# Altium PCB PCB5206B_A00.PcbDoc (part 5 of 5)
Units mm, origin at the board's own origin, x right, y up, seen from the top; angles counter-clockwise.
Board outline 115 x 60 mm, 6 copper layers (Top Layer, GND Layer 2, Signal Layer 3, Signal Layer 4, VCC Layer 5, Bottom Layer), stack 1.555 mm thick; 384 components, 267 nets, 1313 pads, 834 vias.
Unrouted connection lines stored in the file: 10.
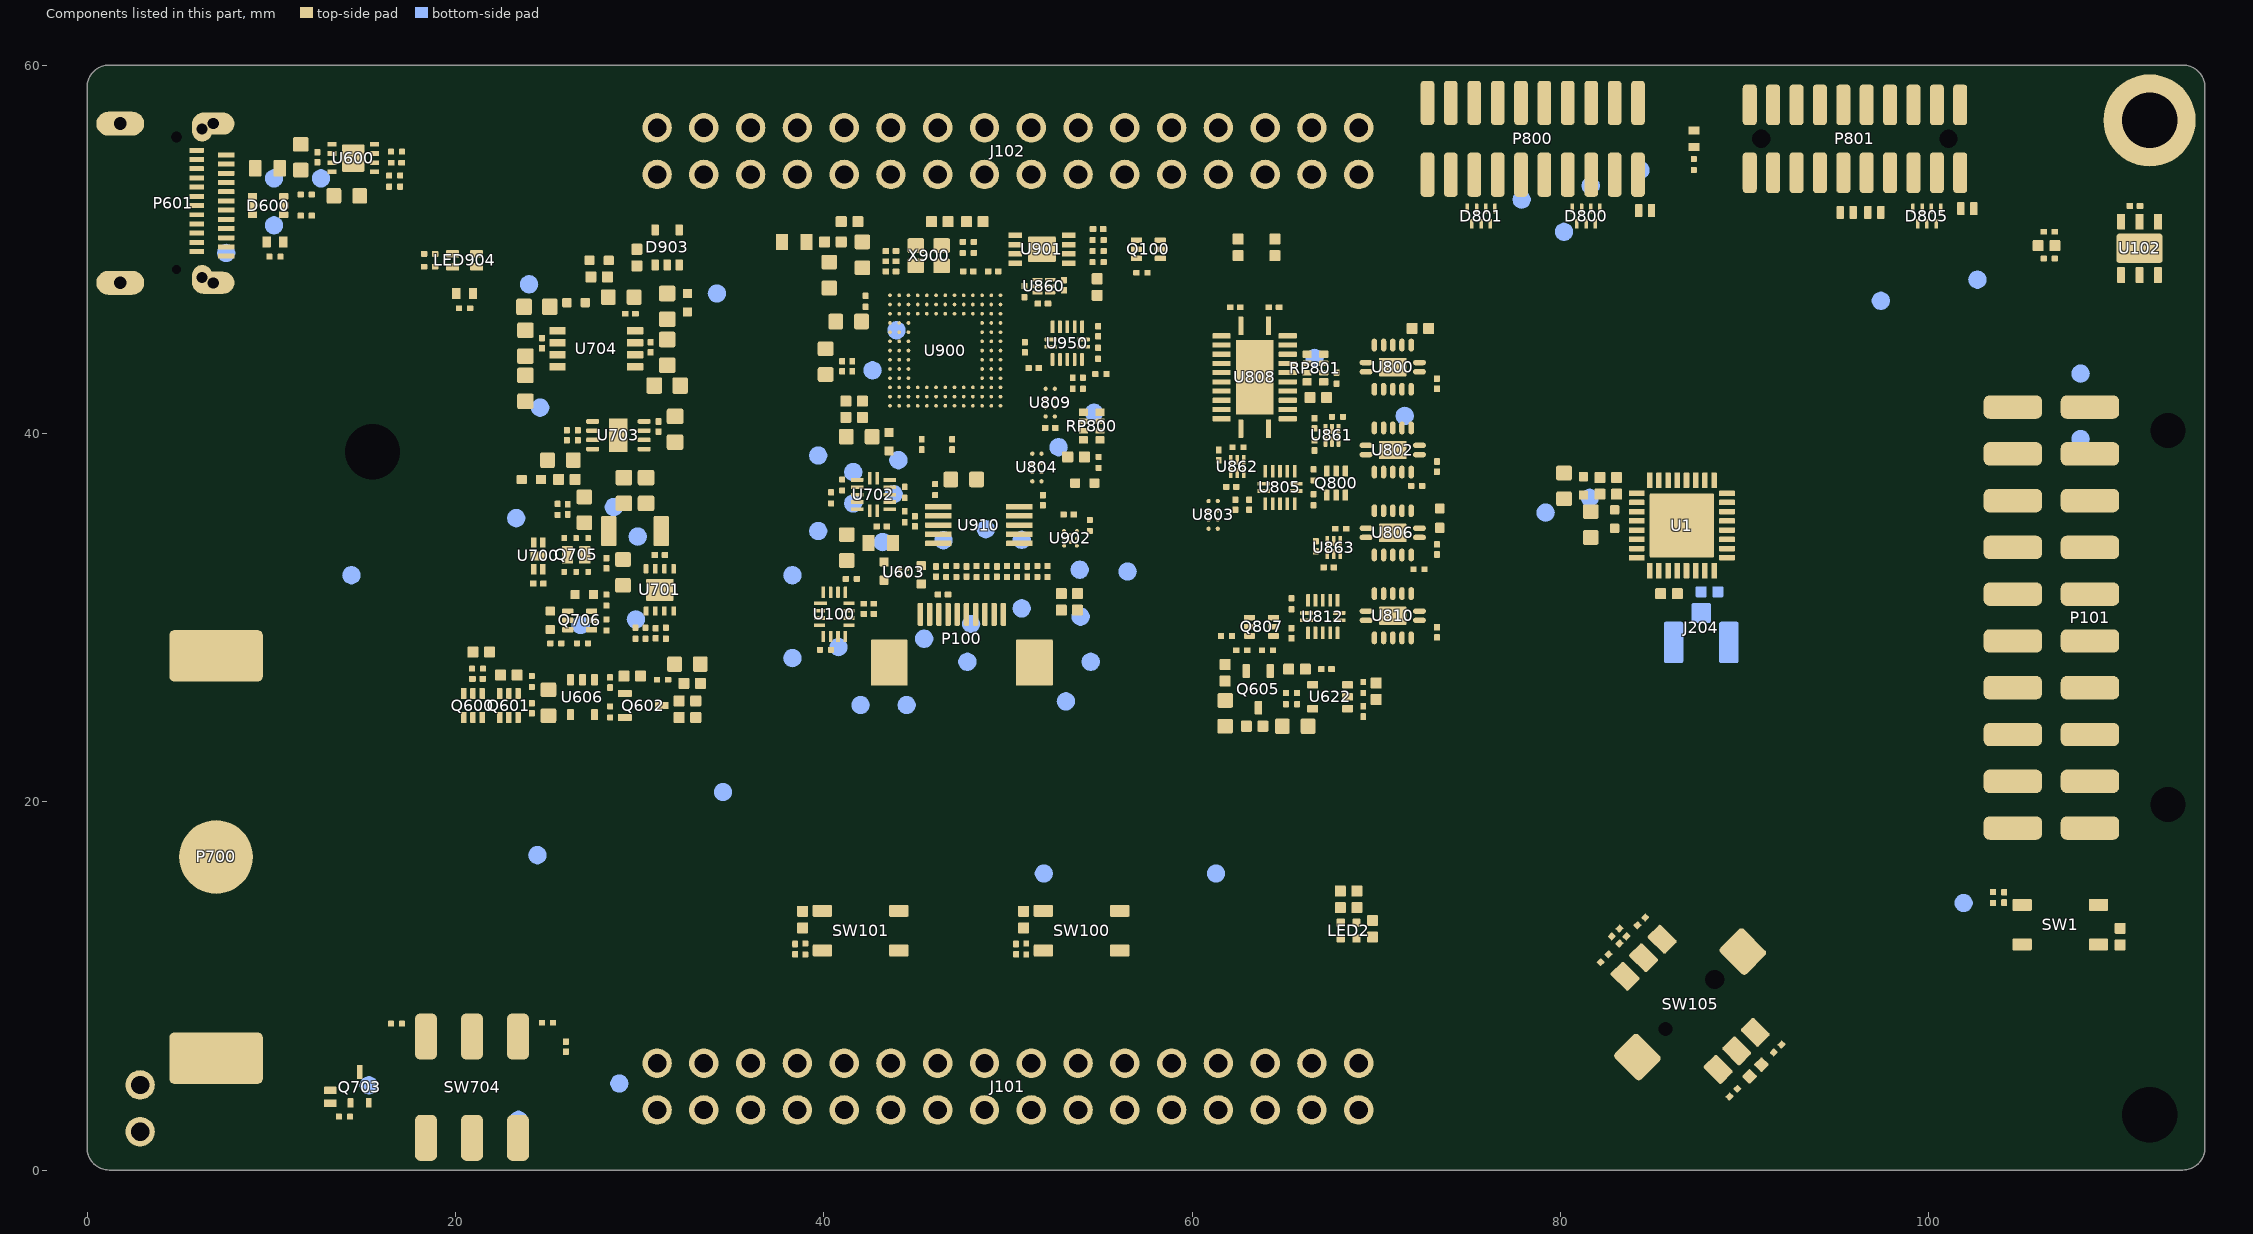
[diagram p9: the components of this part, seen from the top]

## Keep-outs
Bottom Layer:
  region: 32.691,5.802 ccw(c33.491,5.802) 33.491,5.002 ccw(c33.491,5.802) 34.291,5.802 ccw(c33.491,5.802) 33.491,6.602 ccw(c33.491,5.802)
  region: 35.231,5.802 ccw(c36.031,5.802) 36.031,5.002 ccw(c36.031,5.802) 36.831,5.802 ccw(c36.031,5.802) 36.031,6.602 ccw(c36.031,5.802)
  region: 37.771,5.802 ccw(c38.571,5.802) 38.571,5.002 ccw(c38.571,5.802) 39.371,5.802 ccw(c38.571,5.802) 38.571,6.602 ccw(c38.571,5.802)
  region: 40.311,5.802 ccw(c41.111,5.802) 41.111,5.002 ccw(c41.111,5.802) 41.911,5.802 ccw(c41.111,5.802) 41.111,6.602 ccw(c41.111,5.802)
  region: 42.851,5.802 ccw(c43.651,5.802) 43.651,5.002 ccw(c43.651,5.802) 44.451,5.802 ccw(c43.651,5.802) 43.651,6.602 ccw(c43.651,5.802)
  region: 45.391,5.802 ccw(c46.191,5.802) 46.191,5.002 ccw(c46.191,5.802) 46.991,5.802 ccw(c46.191,5.802) 46.191,6.602 ccw(c46.191,5.802)
  region: 47.931,5.802 ccw(c48.731,5.802) 48.731,5.002 ccw(c48.731,5.802) 49.531,5.802 ccw(c48.731,5.802) 48.731,6.602 ccw(c48.731,5.802)
  region: 50.471,5.802 ccw(c51.271,5.802) 51.271,5.002 ccw(c51.271,5.802) 52.071,5.802 ccw(c51.271,5.802) 51.271,6.602 ccw(c51.271,5.802)
  region: 53.011,5.802 ccw(c53.811,5.802) 53.811,5.002 ccw(c53.811,5.802) 54.611,5.802 ccw(c53.811,5.802) 53.811,6.602 ccw(c53.811,5.802)
  region: 55.551,5.802 ccw(c56.351,5.802) 56.351,5.002 ccw(c56.351,5.802) 57.151,5.802 ccw(c56.351,5.802) 56.351,6.602 ccw(c56.351,5.802)
  region: 58.091,5.802 ccw(c58.891,5.802) 58.891,5.002 ccw(c58.891,5.802) 59.691,5.802 ccw(c58.891,5.802) 58.891,6.602 ccw(c58.891,5.802)
  region: 60.631,5.802 ccw(c61.431,5.802) 61.431,5.002 ccw(c61.431,5.802) 62.231,5.802 ccw(c61.431,5.802) 61.431,6.602 ccw(c61.431,5.802)
  region: 63.171,5.802 ccw(c63.971,5.802) 63.971,5.002 ccw(c63.971,5.802) 64.771,5.802 ccw(c63.971,5.802) 63.971,6.602 ccw(c63.971,5.802)
  region: 65.711,5.802 ccw(c66.511,5.802) 66.511,5.002 ccw(c66.511,5.802) 67.311,5.802 ccw(c66.511,5.802) 66.511,6.602 ccw(c66.511,5.802)
  region: 68.251,5.802 ccw(c69.051,5.802) 69.051,5.002 ccw(c69.051,5.802) 69.851,5.802 ccw(c69.051,5.802) 69.051,6.602 ccw(c69.051,5.802)
  region: 30.151,5.802 ccw(c30.951,5.802) 30.951,5.002 ccw(c30.951,5.802) 31.751,5.802 ccw(c30.951,5.802) 30.951,6.602 ccw(c30.951,5.802)
  region: 30.151,3.262 ccw(c30.951,3.262) 30.951,2.462 ccw(c30.951,3.262) 31.751,3.262 ccw(c30.951,3.262) 30.951,4.062 ccw(c30.951,3.262)
  region: 30.151,3.262 ccw(c30.951,3.262) 30.951,2.462 ccw(c30.951,3.262) 31.751,3.262 ccw(c30.951,3.262) 30.951,4.062 ccw(c30.951,3.262)
  region: 32.691,3.262 ccw(c33.491,3.262) 33.491,2.462 ccw(c33.491,3.262) 34.291,3.262 ccw(c33.491,3.262) 33.491,4.062 ccw(c33.491,3.262)
  region: 35.231,3.262 ccw(c36.031,3.262) 36.031,2.462 ccw(c36.031,3.262) 36.831,3.262 ccw(c36.031,3.262) 36.031,4.062 ccw(c36.031,3.262)
  region: 37.771,3.262 ccw(c38.571,3.262) 38.571,2.462 ccw(c38.571,3.262) 39.371,3.262 ccw(c38.571,3.262) 38.571,4.062 ccw(c38.571,3.262)
  region: 40.311,3.262 ccw(c41.111,3.262) 41.111,2.462 ccw(c41.111,3.262) 41.911,3.262 ccw(c41.111,3.262) 41.111,4.062 ccw(c41.111,3.262)
  region: 42.851,3.262 ccw(c43.651,3.262) 43.651,2.462 ccw(c43.651,3.262) 44.451,3.262 ccw(c43.651,3.262) 43.651,4.062 ccw(c43.651,3.262)
  region: 45.391,3.262 ccw(c46.191,3.262) 46.191,2.462 ccw(c46.191,3.262) 46.991,3.262 ccw(c46.191,3.262) 46.191,4.062 ccw(c46.191,3.262)
  region: 47.931,3.262 ccw(c48.731,3.262) 48.731,2.462 ccw(c48.731,3.262) 49.531,3.262 ccw(c48.731,3.262) 48.731,4.062 ccw(c48.731,3.262)
  region: 50.471,3.262 ccw(c51.271,3.262) 51.271,2.462 ccw(c51.271,3.262) 52.071,3.262 ccw(c51.271,3.262) 51.271,4.062 ccw(c51.271,3.262)
  region: 53.011,3.262 ccw(c53.811,3.262) 53.811,2.462 ccw(c53.811,3.262) 54.611,3.262 ccw(c53.811,3.262) 53.811,4.062 ccw(c53.811,3.262)
  region: 55.551,3.262 ccw(c56.351,3.262) 56.351,2.462 ccw(c56.351,3.262) 57.151,3.262 ccw(c56.351,3.262) 56.351,4.062 ccw(c56.351,3.262)
  region: 58.091,3.262 ccw(c58.891,3.262) 58.891,2.462 ccw(c58.891,3.262) 59.691,3.262 ccw(c58.891,3.262) 58.891,4.062 ccw(c58.891,3.262)
  region: 60.631,3.262 ccw(c61.431,3.262) 61.431,2.462 ccw(c61.431,3.262) 62.231,3.262 ccw(c61.431,3.262) 61.431,4.062 ccw(c61.431,3.262)
  region: 63.171,3.262 ccw(c63.971,3.262) 63.971,2.462 ccw(c63.971,3.262) 64.771,3.262 ccw(c63.971,3.262) 63.971,4.062 ccw(c63.971,3.262)
  region: 65.711,3.262 ccw(c66.511,3.262) 66.511,2.462 ccw(c66.511,3.262) 67.311,3.262 ccw(c66.511,3.262) 66.511,4.062 ccw(c66.511,3.262)
  region: 68.251,3.262 ccw(c69.051,3.262) 69.051,2.462 ccw(c69.051,3.262) 69.851,3.262 ccw(c69.051,3.262) 69.051,4.062 ccw(c69.051,3.262)
  region: 32.691,56.602 ccw(c33.491,56.602) 33.491,55.802 ccw(c33.491,56.602) 34.291,56.602 ccw(c33.491,56.602) 33.491,57.402 ccw(c33.491,56.602)
  region: 35.231,56.602 ccw(c36.031,56.602) 36.031,55.802 ccw(c36.031,56.602) 36.831,56.602 ccw(c36.031,56.602) 36.031,57.402 ccw(c36.031,56.602)
  region: 37.771,56.602 ccw(c38.571,56.602) 38.571,55.802 ccw(c38.571,56.602) 39.371,56.602 ccw(c38.571,56.602) 38.571,57.402 ccw(c38.571,56.602)
  region: 40.311,56.602 ccw(c41.111,56.602) 41.111,55.802 ccw(c41.111,56.602) 41.911,56.602 ccw(c41.111,56.602) 41.111,57.402 ccw(c41.111,56.602)
  region: 42.851,56.602 ccw(c43.651,56.602) 43.651,55.802 ccw(c43.651,56.602) 44.451,56.602 ccw(c43.651,56.602) 43.651,57.402 ccw(c43.651,56.602)
  region: 45.391,56.602 ccw(c46.191,56.602) 46.191,55.802 ccw(c46.191,56.602) 46.991,56.602 ccw(c46.191,56.602) 46.191,57.402 ccw(c46.191,56.602)
  region: 47.931,56.602 ccw(c48.731,56.602) 48.731,55.802 ccw(c48.731,56.602) 49.531,56.602 ccw(c48.731,56.602) 48.731,57.402 ccw(c48.731,56.602)
  region: 50.471,56.602 ccw(c51.271,56.602) 51.271,55.802 ccw(c51.271,56.602) 52.071,56.602 ccw(c51.271,56.602) 51.271,57.402 ccw(c51.271,56.602)
  region: 53.011,56.602 ccw(c53.811,56.602) 53.811,55.802 ccw(c53.811,56.602) 54.611,56.602 ccw(c53.811,56.602) 53.811,57.402 ccw(c53.811,56.602)
  region: 55.551,56.602 ccw(c56.351,56.602) 56.351,55.802 ccw(c56.351,56.602) 57.151,56.602 ccw(c56.351,56.602) 56.351,57.402 ccw(c56.351,56.602)
  region: 58.091,56.602 ccw(c58.891,56.602) 58.891,55.802 ccw(c58.891,56.602) 59.691,56.602 ccw(c58.891,56.602) 58.891,57.402 ccw(c58.891,56.602)
  region: 60.631,56.602 ccw(c61.431,56.602) 61.431,55.802 ccw(c61.431,56.602) 62.231,56.602 ccw(c61.431,56.602) 61.431,57.402 ccw(c61.431,56.602)
  region: 63.171,56.602 ccw(c63.971,56.602) 63.971,55.802 ccw(c63.971,56.602) 64.771,56.602 ccw(c63.971,56.602) 63.971,57.402 ccw(c63.971,56.602)
  region: 65.711,56.602 ccw(c66.511,56.602) 66.511,55.802 ccw(c66.511,56.602) 67.311,56.602 ccw(c66.511,56.602) 66.511,57.402 ccw(c66.511,56.602)
  region: 68.251,56.602 ccw(c69.051,56.602) 69.051,55.802 ccw(c69.051,56.602) 69.851,56.602 ccw(c69.051,56.602) 69.051,57.402 ccw(c69.051,56.602)
  region: 30.151,56.602 ccw(c30.951,56.602) 30.951,55.802 ccw(c30.951,56.602) 31.751,56.602 ccw(c30.951,56.602) 30.951,57.402 ccw(c30.951,56.602)
  region: 30.151,54.062 ccw(c30.951,54.062) 30.951,53.262 ccw(c30.951,54.062) 31.751,54.062 ccw(c30.951,54.062) 30.951,54.862 ccw(c30.951,54.062)
  region: 30.151,54.062 ccw(c30.951,54.062) 30.951,53.262 ccw(c30.951,54.062) 31.751,54.062 ccw(c30.951,54.062) 30.951,54.862 ccw(c30.951,54.062)
  region: 32.691,54.062 ccw(c33.491,54.062) 33.491,53.262 ccw(c33.491,54.062) 34.291,54.062 ccw(c33.491,54.062) 33.491,54.862 ccw(c33.491,54.062)
  region: 35.231,54.062 ccw(c36.031,54.062) 36.031,53.262 ccw(c36.031,54.062) 36.831,54.062 ccw(c36.031,54.062) 36.031,54.862 ccw(c36.031,54.062)
  region: 37.771,54.062 ccw(c38.571,54.062) 38.571,53.262 ccw(c38.571,54.062) 39.371,54.062 ccw(c38.571,54.062) 38.571,54.862 ccw(c38.571,54.062)
  region: 40.311,54.062 ccw(c41.111,54.062) 41.111,53.262 ccw(c41.111,54.062) 41.911,54.062 ccw(c41.111,54.062) 41.111,54.862 ccw(c41.111,54.062)
  region: 42.851,54.062 ccw(c43.651,54.062) 43.651,53.262 ccw(c43.651,54.062) 44.451,54.062 ccw(c43.651,54.062) 43.651,54.862 ccw(c43.651,54.062)
  region: 45.391,54.062 ccw(c46.191,54.062) 46.191,53.262 ccw(c46.191,54.062) 46.991,54.062 ccw(c46.191,54.062) 46.191,54.862 ccw(c46.191,54.062)
  region: 47.931,54.062 ccw(c48.731,54.062) 48.731,53.262 ccw(c48.731,54.062) 49.531,54.062 ccw(c48.731,54.062) 48.731,54.862 ccw(c48.731,54.062)
  region: 50.471,54.062 ccw(c51.271,54.062) 51.271,53.262 ccw(c51.271,54.062) 52.071,54.062 ccw(c51.271,54.062) 51.271,54.862 ccw(c51.271,54.062)
  region: 53.011,54.062 ccw(c53.811,54.062) 53.811,53.262 ccw(c53.811,54.062) 54.611,54.062 ccw(c53.811,54.062) 53.811,54.862 ccw(c53.811,54.062)
  region: 55.551,54.062 ccw(c56.351,54.062) 56.351,53.262 ccw(c56.351,54.062) 57.151,54.062 ccw(c56.351,54.062) 56.351,54.862 ccw(c56.351,54.062)
  region: 58.091,54.062 ccw(c58.891,54.062) 58.891,53.262 ccw(c58.891,54.062) 59.691,54.062 ccw(c58.891,54.062) 58.891,54.862 ccw(c58.891,54.062)
  region: 60.631,54.062 ccw(c61.431,54.062) 61.431,53.262 ccw(c61.431,54.062) 62.231,54.062 ccw(c61.431,54.062) 61.431,54.862 ccw(c61.431,54.062)
  region: 63.171,54.062 ccw(c63.971,54.062) 63.971,53.262 ccw(c63.971,54.062) 64.771,54.062 ccw(c63.971,54.062) 63.971,54.862 ccw(c63.971,54.062)
  region: 65.711,54.062 ccw(c66.511,54.062) 66.511,53.262 ccw(c66.511,54.062) 67.311,54.062 ccw(c66.511,54.062) 66.511,54.862 ccw(c66.511,54.062)
  region: 68.251,54.062 ccw(c69.051,54.062) 69.051,53.262 ccw(c69.051,54.062) 69.851,54.062 ccw(c69.051,54.062) 69.051,54.862 ccw(c69.051,54.062)
  region: 45.391,54.062 ccw(c46.191,54.062) 46.191,53.262 ccw(c46.191,54.062) 46.991,54.062 ccw(c46.191,54.062) 46.191,54.862 ccw(c46.191,54.062)
  region: 42.851,54.062 ccw(c43.651,54.062) 43.651,53.262 ccw(c43.651,54.062) 44.451,54.062 ccw(c43.651,54.062) 43.651,54.862 ccw(c43.651,54.062)
  region: 40.311,54.062 ccw(c41.111,54.062) 41.111,53.262 ccw(c41.111,54.062) 41.911,54.062 ccw(c41.111,54.062) 41.111,54.862 ccw(c41.111,54.062)
  region: 37.771,54.062 ccw(c38.571,54.062) 38.571,53.262 ccw(c38.571,54.062) 39.371,54.062 ccw(c38.571,54.062) 38.571,54.862 ccw(c38.571,54.062)
  region: 35.231,54.062 ccw(c36.031,54.062) 36.031,53.262 ccw(c36.031,54.062) 36.831,54.062 ccw(c36.031,54.062) 36.031,54.862 ccw(c36.031,54.062)
  region: 32.691,54.062 ccw(c33.491,54.062) 33.491,53.262 ccw(c33.491,54.062) 34.291,54.062 ccw(c33.491,54.062) 33.491,54.862 ccw(c33.491,54.062)
  region: 30.151,54.062 ccw(c30.951,54.062) 30.951,53.262 ccw(c30.951,54.062) 31.751,54.062 ccw(c30.951,54.062) 30.951,54.862 ccw(c30.951,54.062)
  region: 30.151,54.062 ccw(c30.951,54.062) 30.951,53.262 ccw(c30.951,54.062) 31.751,54.062 ccw(c30.951,54.062) 30.951,54.862 ccw(c30.951,54.062)
  region: 30.151,56.602 ccw(c30.951,56.602) 30.951,55.802 ccw(c30.951,56.602) 31.751,56.602 ccw(c30.951,56.602) 30.951,57.402 ccw(c30.951,56.602)
  region: 45.391,56.602 ccw(c46.191,56.602) 46.191,55.802 ccw(c46.191,56.602) 46.991,56.602 ccw(c46.191,56.602) 46.191,57.402 ccw(c46.191,56.602)
  region: 42.851,56.602 ccw(c43.651,56.602) 43.651,55.802 ccw(c43.651,56.602) 44.451,56.602 ccw(c43.651,56.602) 43.651,57.402 ccw(c43.651,56.602)
  region: 40.311,56.602 ccw(c41.111,56.602) 41.111,55.802 ccw(c41.111,56.602) 41.911,56.602 ccw(c41.111,56.602) 41.111,57.402 ccw(c41.111,56.602)
  region: 37.771,56.602 ccw(c38.571,56.602) 38.571,55.802 ccw(c38.571,56.602) 39.371,56.602 ccw(c38.571,56.602) 38.571,57.402 ccw(c38.571,56.602)
  region: 35.231,56.602 ccw(c36.031,56.602) 36.031,55.802 ccw(c36.031,56.602) 36.831,56.602 ccw(c36.031,56.602) 36.031,57.402 ccw(c36.031,56.602)
  region: 32.691,56.602 ccw(c33.491,56.602) 33.491,55.802 ccw(c33.491,56.602) 34.291,56.602 ccw(c33.491,56.602) 33.491,57.402 ccw(c33.491,56.602)
  region: 68.251,3.262 ccw(c69.051,3.262) 69.051,2.462 ccw(c69.051,3.262) 69.851,3.262 ccw(c69.051,3.262) 69.051,4.062 ccw(c69.051,3.262)
  region: 65.711,3.262 ccw(c66.511,3.262) 66.511,2.462 ccw(c66.511,3.262) 67.311,3.262 ccw(c66.511,3.262) 66.511,4.062 ccw(c66.511,3.262)
  region: 60.631,3.262 ccw(c61.431,3.262) 61.431,2.462 ccw(c61.431,3.262) 62.231,3.262 ccw(c61.431,3.262) 61.431,4.062 ccw(c61.431,3.262)
  region: 58.091,3.262 ccw(c58.891,3.262) 58.891,2.462 ccw(c58.891,3.262) 59.691,3.262 ccw(c58.891,3.262) 58.891,4.062 ccw(c58.891,3.262)
  region: 40.311,3.262 ccw(c41.111,3.262) 41.111,2.462 ccw(c41.111,3.262) 41.911,3.262 ccw(c41.111,3.262) 41.111,4.062 ccw(c41.111,3.262)
  region: 37.771,3.262 ccw(c38.571,3.262) 38.571,2.462 ccw(c38.571,3.262) 39.371,3.262 ccw(c38.571,3.262) 38.571,4.062 ccw(c38.571,3.262)
  region: 35.231,3.262 ccw(c36.031,3.262) 36.031,2.462 ccw(c36.031,3.262) 36.831,3.262 ccw(c36.031,3.262) 36.031,4.062 ccw(c36.031,3.262)
  region: 32.691,3.262 ccw(c33.491,3.262) 33.491,2.462 ccw(c33.491,3.262) 34.291,3.262 ccw(c33.491,3.262) 33.491,4.062 ccw(c33.491,3.262)
  region: 30.151,3.262 ccw(c30.951,3.262) 30.951,2.462 ccw(c30.951,3.262) 31.751,3.262 ccw(c30.951,3.262) 30.951,4.062 ccw(c30.951,3.262)
  region: 30.151,3.262 ccw(c30.951,3.262) 30.951,2.462 ccw(c30.951,3.262) 31.751,3.262 ccw(c30.951,3.262) 30.951,4.062 ccw(c30.951,3.262)
  region: 30.151,5.802 ccw(c30.951,5.802) 30.951,5.002 ccw(c30.951,5.802) 31.751,5.802 ccw(c30.951,5.802) 30.951,6.602 ccw(c30.951,5.802)
  region: 68.251,5.802 ccw(c69.051,5.802) 69.051,5.002 ccw(c69.051,5.802) 69.851,5.802 ccw(c69.051,5.802) 69.051,6.602 ccw(c69.051,5.802)
  region: 65.711,5.802 ccw(c66.511,5.802) 66.511,5.002 ccw(c66.511,5.802) 67.311,5.802 ccw(c66.511,5.802) 66.511,6.602 ccw(c66.511,5.802)
  region: 63.171,5.802 ccw(c63.971,5.802) 63.971,5.002 ccw(c63.971,5.802) 64.771,5.802 ccw(c63.971,5.802) 63.971,6.602 ccw(c63.971,5.802)
  region: 60.631,5.802 ccw(c61.431,5.802) 61.431,5.002 ccw(c61.431,5.802) 62.231,5.802 ccw(c61.431,5.802) 61.431,6.602 ccw(c61.431,5.802)
  region: 58.091,5.802 ccw(c58.891,5.802) 58.891,5.002 ccw(c58.891,5.802) 59.691,5.802 ccw(c58.891,5.802) 58.891,6.602 ccw(c58.891,5.802)
  region: 40.311,5.802 ccw(c41.111,5.802) 41.111,5.002 ccw(c41.111,5.802) 41.911,5.802 ccw(c41.111,5.802) 41.111,6.602 ccw(c41.111,5.802)
  region: 37.771,5.802 ccw(c38.571,5.802) 38.571,5.002 ccw(c38.571,5.802) 39.371,5.802 ccw(c38.571,5.802) 38.571,6.602 ccw(c38.571,5.802)
  region: 35.231,5.802 ccw(c36.031,5.802) 36.031,5.002 ccw(c36.031,5.802) 36.831,5.802 ccw(c36.031,5.802) 36.031,6.602 ccw(c36.031,5.802)
  region: 32.691,5.802 ccw(c33.491,5.802) 33.491,5.002 ccw(c33.491,5.802) 34.291,5.802 ccw(c33.491,5.802) 33.491,6.602 ccw(c33.491,5.802)
  region: 103.5,19 cw(c103.5,18.5) 104,18.5 cw(c103.5,18.5) 103.5,18 cw(c103.5,18.5) 103,18.5 cw(c103.5,18.5)
  region: 108.25,40.2 cw(c108.25,39.699) 108.75,39.7 cw(c108.25,39.7) 108.25,39.2 cw(c108.25,39.7) 107.75,39.7 cw(c108.25,39.699)
  region: 108.25,43.748 cw(c108.25,43.248) 108.75,43.248 cw(c108.25,43.248) 108.25,42.748 cw(c108.25,43.248) 107.75,43.248 cw(c108.25,43.248)
  region: 107,54.2 cw(c107,53.7) 107.5,53.7 cw(c107,53.7) 107,53.2 cw(c107,53.7) 106.5,53.7 cw(c107,53.7)
  region: 105.4,52.498 cw(c105.4,51.998) 105.9,51.998 cw(c105.4,51.998) 105.4,51.498 cw(c105.4,51.998) 104.9,51.998 cw(c105.4,51.998)
  region: 104.45,54.2 cw(c104.45,53.7) 104.95,53.7 cw(c104.45,53.7) 104.45,53.2 cw(c104.45,53.7) 103.95,53.7 cw(c104.45,53.7)
  region: 103.399,52.498 cw(c103.399,51.998) 103.899,51.998 cw(c103.399,51.998) 103.399,51.498 cw(c103.399,51.998) 102.899,51.998 cw(c103.399,51.998)
  region: 102.649,48.848 cw(c102.649,48.348) 103.149,48.348 cw(c102.649,48.348) 102.649,47.848 cw(c102.649,48.348) 102.149,48.348 cw(c102.649,48.348)
  region: 97.399,47.7 cw(c97.399,47.2) 97.899,47.2 cw(c97.399,47.2) 97.399,46.7 cw(c97.399,47.2) 96.899,47.2 cw(c97.399,47.2)
  region: 92.525,52.432 cw(c92.525,51.932) 93.025,51.932 cw(c92.525,51.932) 92.525,51.432 cw(c92.525,51.932) 92.025,51.932 cw(c92.525,51.932)
  region: 93.541,54.21 cw(c93.541,53.71) 94.041,53.71 cw(c93.541,53.71) 93.541,53.21 cw(c93.541,53.71) 93.041,53.71 cw(c93.541,53.71)
  region: 90.493,52.432 cw(c90.493,51.932) 90.993,51.932 cw(c90.493,51.932) 90.493,51.432 cw(c90.493,51.932) 89.993,51.932 cw(c90.493,51.932)
  region: 88.461,52.432 cw(c88.461,51.932) 88.961,51.932 cw(c88.461,51.932) 88.461,51.432 cw(c88.461,51.932) 87.961,51.932 cw(c88.461,51.932)
  region: 89.477,54.21 cw(c89.477,53.71) 89.977,53.71 cw(c89.477,53.71) 89.477,53.21 cw(c89.477,53.71) 88.977,53.71 cw(c89.477,53.71)
  region: 87.466,54.206 cw(c87.467,53.706) 87.967,53.706 cw(c87.466,53.707) 87.466,53.206 cw(c87.466,53.706) 86.967,53.706 cw(c87.467,53.706)
  region: 84.349,54.799 cw(c84.349,54.299) 84.849,54.3 cw(c84.349,54.3) 84.349,53.799 cw(c84.349,54.299) 83.849,54.299 cw(c84.349,54.299)
  region: 85.4,52.198 cw(c85.4,51.698) 85.9,51.699 cw(c85.4,51.699) 85.4,51.199 cw(c85.4,51.698) 84.9,51.698 cw(c85.4,51.698)
  region: 93.449,42.798 cw(c93.45,42.298) 93.95,42.298 cw(c93.449,42.298) 93.449,41.798 cw(c93.449,42.298) 92.949,42.298 cw(c93.45,42.298)
  region: 86.15,40.05 cw(c86.15,39.55) 86.65,39.55 cw(c86.149,39.55) 86.149,39.05 cw(c86.149,39.55) 85.65,39.55 cw(c86.15,39.55)
  region: 81.649,53.949 cw(c81.649,53.449) 82.149,53.449 cw(c81.649,53.449) 81.649,52.949 cw(c81.649,53.449) 81.149,53.449 cw(c81.649,53.448)
  region: 77.9,53.199 cw(c77.9,52.699) 78.4,52.699 cw(c77.9,52.699) 77.9,52.199 cw(c77.9,52.699) 77.4,52.699 cw(c77.9,52.699)
  region: 80.201,51.449 cw(c80.201,50.949) 80.701,50.949 cw(c80.201,50.949) 80.201,50.449 cw(c80.201,50.949) 79.701,50.949 cw(c80.201,50.949)
  region: 77.399,48.498 cw(c77.399,47.998) 77.899,47.998 cw(c77.399,47.998) 77.399,47.498 cw(c77.399,47.998) 76.899,47.998 cw(c77.399,47.998)
  region: 75.4,48.498 cw(c75.4,47.998) 75.9,47.998 cw(c75.4,47.998) 75.4,47.498 cw(c75.4,47.998) 74.9,47.998 cw(c75.4,47.998)
  region: 73.399,48.498 cw(c73.399,47.998) 73.899,47.998 cw(c73.399,47.998) 73.399,47.498 cw(c73.399,47.998) 72.899,47.998 cw(c73.399,47.998)
  region: 77.399,46.298 cw(c77.399,45.798) 77.899,45.798 cw(c77.399,45.798) 77.399,45.298 cw(c77.399,45.798) 76.899,45.798 cw(c77.399,45.798)
  region: 75.4,46.298 cw(c75.4,45.798) 75.9,45.798 cw(c75.4,45.798) 75.4,45.298 cw(c75.4,45.798) 74.9,45.798 cw(c75.4,45.798)
  region: 73.399,46.298 cw(c73.399,45.798) 73.899,45.798 cw(c73.399,45.798) 73.399,45.298 cw(c73.399,45.798) 72.899,45.798 cw(c73.399,45.798)
  region: 71.4,46.298 cw(c71.4,45.798) 71.9,45.798 cw(c71.4,45.798) 71.4,45.298 cw(c71.4,45.798) 70.9,45.798 cw(c71.4,45.798)
  region: 73.399,43.598 cw(c73.399,43.098) 73.899,43.098 cw(c73.399,43.098) 73.399,42.598 cw(c73.399,43.098) 72.899,43.098 cw(c73.399,43.098)
  region: 71.55,41.449 cw(c71.55,40.949) 72.05,40.949 cw(c71.55,40.949) 71.55,40.449 cw(c71.55,40.949) 71.05,40.949 cw(c71.55,40.949)
  region: 66.65,44.599 cw(c66.65,44.099) 67.15,44.099 cw(c66.65,44.099) 66.65,43.599 cw(c66.65,44.099) 66.15,44.099 cw(c66.65,44.099)
  region: 94.199,12.348 cw(c94.199,11.848) 94.699,11.848 cw(c94.199,11.849) 94.199,11.348 cw(c94.199,11.848) 93.699,11.848 cw(c94.199,11.848)
  region: 96.8,11.8 cw(c96.8,11.3) 97.3,11.3 cw(c96.8,11.3) 96.8,10.8 cw(c96.8,11.3) 96.3,11.3 cw(c96.8,11.3)
  region: 93.249,9.948 cw(c93.249,9.448) 93.749,9.448 cw(c93.249,9.448) 93.249,8.948 cw(c93.249,9.448) 92.749,9.448 cw(c93.249,9.448)
  region: 96.5,9.148 cw(c96.5,8.648) 97,8.648 cw(c96.5,8.648) 96.5,8.148 cw(c96.5,8.648) 96,8.648 cw(c96.5,8.648)
  region: 95.7,6.55 cw(c95.7,6.05) 96.2,6.05 cw(c95.7,6.05) 95.7,5.55 cw(c95.7,6.05) 95.2,6.05 cw(c95.7,6.049)
  region: 93.249,7.398 cw(c93.249,6.898) 93.749,6.898 cw(c93.249,6.898) 93.249,6.398 cw(c93.249,6.898) 92.749,6.898 cw(c93.249,6.898)
  region: 81.499,10.949 cw(c81.499,10.449) 81.999,10.449 cw(c81.499,10.449) 81.499,9.949 cw(c81.499,10.449) 80.999,10.449 cw(c81.499,10.449)
  region: 77.249,10.949 cw(c77.249,10.449) 77.749,10.449 cw(c77.249,10.449) 77.249,9.949 cw(c77.249,10.449) 76.749,10.449 cw(c77.249,10.449)
  region: 72.949,10.949 cw(c72.949,10.449) 73.449,10.449 cw(c72.949,10.449) 72.949,9.949 cw(c72.949,10.449) 72.449,10.449 cw(c72.949,10.449)
  region: 74.1,6.748 cw(c74.1,6.248) 74.6,6.248 cw(c74.1,6.248) 74.1,5.748 cw(c74.1,6.248) 73.6,6.248 cw(c74.1,6.248)
  region: 54.674,41.624 cw(c54.674,41.124) 55.174,41.125 cw(c54.674,41.125) 54.674,40.625 cw(c54.674,41.124) 54.174,41.124 cw(c54.674,41.124)
  region: 52.749,39.75 cw(c52.749,39.25) 53.249,39.25 cw(c52.748,39.25) 52.748,38.75 cw(c52.748,39.25) 52.249,39.25 cw(c52.749,39.25)
  region: 50.75,34.723 cw(c50.75,34.223) 51.25,34.223 cw(c50.749,34.223) 50.75,33.723 cw(c50.75,34.223) 50.25,34.223 cw(c50.75,34.223)
  region: 53.899,33.098 cw(c53.899,32.598) 54.399,32.598 cw(c53.899,32.598) 53.899,32.098 cw(c53.899,32.598) 53.399,32.598 cw(c53.899,32.598)
  region: 50.75,31 cw(c50.75,30.5) 51.25,30.5 cw(c50.749,30.5) 50.75,30 cw(c50.75,30.5) 50.25,30.5 cw(c50.75,30.5)
  region: 53.95,30.55 cw(c53.95,30.05) 54.45,30.05 cw(c53.95,30.05) 53.95,29.55 cw(c53.95,30.05) 53.45,30.05 cw(c53.95,30.05)
  region: 54.499,28.099 cw(c54.499,27.599) 54.999,27.599 cw(c54.498,27.599) 54.499,27.099 cw(c54.499,27.599) 53.999,27.599 cw(c54.499,27.599)
  region: 51.799,28.099 cw(c51.799,27.599) 52.299,27.599 cw(c51.798,27.599) 51.799,27.099 cw(c51.799,27.599) 51.299,27.599 cw(c51.799,27.599)
  region: 53.15,25.95 cw(c53.15,25.45) 53.65,25.45 cw(c53.15,25.45) 53.15,24.95 cw(c53.15,25.45) 52.65,25.45 cw(c53.15,25.45)
  region: 47.999,30.149 cw(c47.999,29.649) 48.499,29.649 cw(c47.999,29.649) 47.999,29.149 cw(c47.999,29.649) 47.499,29.649 cw(c47.999,29.649)
  region: 45.449,29.349 cw(c45.449,28.849) 45.949,28.849 cw(c45.448,28.849) 45.449,28.349 cw(c45.449,28.849) 44.949,28.849 cw(c45.449,28.849)
  region: 47,25.749 cw(c47.001,25.249) 47.501,25.25 cw(c47,25.25) 47,24.75 cw(c47,25.249) 46.501,25.249 cw(c47.001,25.249)
  region: 43.249,28 cw(c43.249,27.5) 43.749,27.5 cw(c43.249,27.5) 43.249,27 cw(c43.249,27.5) 42.749,27.5 cw(c43.249,27.5)
  region: 44.499,25.749 cw(c44.499,25.249) 44.999,25.25 cw(c44.499,25.25) 44.499,24.75 cw(c44.499,25.249) 43.999,25.249 cw(c44.499,25.249)
  region: 41.999,25.749 cw(c41.999,25.249) 42.499,25.25 cw(c41.999,25.25) 41.999,24.75 cw(c41.999,25.249) 41.499,25.249 cw(c41.999,25.249)
  region: 61.301,16.598 cw(c61.301,16.098) 61.801,16.098 cw(c61.301,16.098) 61.301,15.598 cw(c61.301,16.098) 60.801,16.098 cw(c61.301,16.098)
  region: 51.951,16.598 cw(c51.951,16.098) 52.451,16.098 cw(c51.951,16.098) 51.951,15.598 cw(c51.951,16.098) 51.451,16.098 cw(c51.951,16.098)
  region: 34.524,21.025 cw(c34.524,20.525) 35.024,20.525 cw(c34.524,20.525) 34.524,20.025 cw(c34.524,20.525) 34.024,20.525 cw(c34.524,20.525)
  region: 24.45,17.599 cw(c24.45,17.099) 24.95,17.099 cw(c24.45,17.099) 24.45,16.599 cw(c24.45,17.099) 23.95,17.099 cw(c24.45,17.098)
  region: 15.649,26.448 cw(c15.649,25.948) 16.149,25.948 cw(c15.649,25.948) 15.649,25.448 cw(c15.649,25.948) 15.149,25.948 cw(c15.649,25.948)
  region: 12.05,26.448 cw(c12.05,25.948) 12.55,25.948 cw(c12.05,25.948) 12.05,25.448 cw(c12.05,25.948) 11.55,25.948 cw(c12.05,25.948)
  region: 12.025,29.773 cw(c12.025,29.273) 12.525,29.273 cw(c12.025,29.273) 12.025,28.773 cw(c12.025,29.273) 11.525,29.273 cw(c12.025,29.273)
  region: 9.475,29.798 cw(c9.475,29.298) 9.975,29.298 cw(c9.474,29.298) 9.475,28.798 cw(c9.475,29.298) 8.975,29.298 cw(c9.475,29.298)
  region: 14.349,32.798 cw(c14.349,32.298) 14.849,32.298 cw(c14.349,32.298) 14.349,31.798 cw(c14.349,32.298) 13.849,32.298 cw(c14.349,32.298)
  region: 10.399,32.249 cw(c10.399,31.749) 10.899,31.749 cw(c10.399,31.75) 10.399,31.249 cw(c10.399,31.749) 9.899,31.749 cw(c10.399,31.749)
  region: 10.399,34.899 cw(c10.399,34.399) 10.899,34.399 cw(c10.399,34.399) 10.399,33.899 cw(c10.399,34.399) 9.899,34.399 cw(c10.399,34.398)
  region: 18.446,49.044 cw(c18.446,48.544) 18.946,48.544 cw(c18.446,48.544) 18.446,48.044 cw(c18.446,48.544) 17.946,48.544 cw(c18.446,48.544)
  region: 15.906,50.314 cw(c15.906,49.814) 16.406,49.814 cw(c15.906,49.814) 15.906,49.314 cw(c15.906,49.814) 15.406,49.814 cw(c15.906,49.814)
  region: 18.446,51.584 cw(c18.446,51.084) 18.946,51.084 cw(c18.446,51.084) 18.446,50.584 cw(c18.446,51.084) 17.946,51.084 cw(c18.446,51.084)
  region: 15.906,52.854 cw(c15.906,52.354) 16.406,52.354 cw(c15.906,52.354) 15.906,51.854 cw(c15.906,52.354) 15.406,52.354 cw(c15.906,52.354)
  region: 18.446,54.124 cw(c18.446,53.624) 18.946,53.624 cw(c18.446,53.624) 18.446,53.124 cw(c18.446,53.624) 17.946,53.624 cw(c18.446,53.624)
  region: 15.906,55.394 cw(c15.906,54.894) 16.406,54.894 cw(c15.906,54.894) 15.906,54.394 cw(c15.906,54.894) 15.406,54.894 cw(c15.906,54.894)
  region: 12.7,54.35 cw(c12.7,53.85) 13.2,53.85 cw(c12.7,53.85) 12.7,53.35 cw(c12.7,53.85) 12.2,53.85 cw(c12.7,53.85)
  region: 10.15,54.35 cw(c10.15,53.85) 10.65,53.85 cw(c10.15,53.85) 10.15,53.35 cw(c10.15,53.85) 9.65,53.85 cw(c10.15,53.85)
  region: 10.15,51.8 cw(c10.15,51.3) 10.65,51.3 cw(c10.15,51.3) 10.15,50.8 cw(c10.15,51.3) 9.65,51.3 cw(c10.15,51.3)
  region: 7.549,50.299 cw(c7.549,49.799) 8.049,49.799 cw(c7.549,49.799) 7.549,49.299 cw(c7.549,49.799) 7.049,49.799 cw(c7.549,49.798)
  region: 24.6,41.899 cw(c24.6,41.399) 25.1,41.399 cw(c24.6,41.399) 24.6,40.899 cw(c24.6,41.399) 24.1,41.399 cw(c24.6,41.399)
  region: 36.249,37.548 cw(c36.249,37.048) 36.749,37.048 cw(c36.249,37.048) 36.249,36.548 cw(c36.249,37.048) 35.749,37.048 cw(c36.249,37.048)
  region: 38.999,37.548 cw(c39,37.048) 39.5,37.048 cw(c38.999,37.048) 38.999,36.548 cw(c38.999,37.048) 38.5,37.048 cw(c39,37.048)
  region: 41.6,38.399 cw(c41.6,37.899) 42.101,37.899 cw(c41.6,37.899) 41.6,37.399 cw(c41.6,37.899) 41.1,37.899 cw(c41.601,37.899)
  region: 44.049,39.049 cw(c44.049,38.549) 44.549,38.549 cw(c44.049,38.549) 44.049,38.049 cw(c44.049,38.549) 43.549,38.549 cw(c44.049,38.549)
  region: 42.649,43.923 cw(c42.65,43.423) 43.15,43.423 cw(c42.649,43.423) 42.649,42.923 cw(c42.649,43.423) 42.149,43.423 cw(c42.65,43.423)
  region: 43.95,46.1 cw(c43.95,45.6) 44.45,45.6 cw(c43.95,45.6) 43.95,45.1 cw(c43.95,45.6) 43.45,45.6 cw(c43.95,45.6)
  region: 18.446,46.504 cw(c18.446,46.004) 18.946,46.004 cw(c18.446,46.004) 18.446,45.504 cw(c18.446,46.004) 17.946,46.004 cw(c18.446,46.004)

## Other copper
Top Layer:
  pour cut-out: 21.7,27.266 22.2,27.266 22.2,26.1 21.7,26.1
  region net N16809528: 10.542,26.275 10.542,29.5 3.462,29.5 3.462,26.275
  region net N16809528: 3.458,7.725 3.458,5.542 4.5,4.5 10.538,4.5 10.538,7.725
Multi-Layer:
  pour cut-out: 114.7,46.2 108.15,46.2 108.15,54.25 114.7,54.25

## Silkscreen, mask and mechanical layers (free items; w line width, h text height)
Top Overlay:
  lines w0.2: 85.2,56 86.65,56 ; 87.85,56 89.3,56
  text "1" at 84.9,58.1 h1.5
  text "1" at 102.5,58.1 h1.5
  text "5V" at 30.35,57.9 h1.2
  text "GND" at 32.4,57.9 h1.2
  text "NC" at 35.3,57.9 h1.2
  text "RST" at 37.6,57.9 h1.2
  text "C2CK" at 39.9,57.9 h1.2
  text "C2D" at 43,57.9 h1.2
  text "NC" at 45.6,57.9 h1.2
  text "NC" at 48,57.9 h1.2
  text "3.7" at 50.6,57.9 h1.2
  text "3.4" at 53.1,57.9 h1.2
  text "3.3" at 55.6,57.9 h1.2
  text "3.2" at 58.2,57.9 h1.2
  text "3.1" at 60.7,57.9 h1.2
  text "3.0" at 63.25,57.9 h1.2
  text "GND" at 65.35,57.9 h1.2
  text "3V3" at 68.15,57.9 h1.2
  text "2" at 102.5,53.1 h1.5
  text "2" at 84.9,52.9 h1.5
  text "5V" at 30.2,52 h1.2
  text "GND" at 32.3,52 h1.2
  text "NC" at 35.4,52 h1.2
  text "NC" at 37.992,52 h1.2
  text "NC" at 40.55,52 h1.2
  text "NC" at 42.9,52 h1.2
  text "NC" at 45.5,52 h1.2
  text "2.6" at 48,52 h1.2
  text "2.5" at 50.55,52 h1.2
  text "2.4" at 53.1,52 h1.2
  text "2.3" at 55.6,52 h1.2
  text "2.2" at 58.2,52 h1.2
  text "2.1" at 60.8,52 h1.2
  text "2.0" at 63.25,52 h1.2
  text "GND" at 65.3,52 h1.2
  text "3V3" at 68.2,52 h1.2
  text "DEBUG" at 76.075,49.1 h1.6
  text "SIMPLICITY" at 92.075,49.1 h1.6
  text "Si7021" at 108.873,44.521 h2
  text "EXP" at 102.947,43.9 h2
  text "EFM8" at 79.6,43.067 h5.4
  text "20" at 103.947,42.3 h1.5
  text "19" at 107.847,42.3 h1.5
  text "Busy Bee" at 79.6,40.487 h3.2
  text "EFM8BB52" at 82.093,28.924 h2.1
  text "2" at 104.347,16.6 h1.5
  text "1" at 108.547,16.6 h1.5
  text "LED0" at 66.374,10.621 h2
  text "RESET" at 104.259,9.721 h2
  text "BTN1" at 39.946,9.6 h2
  text "BTN0" at 51.825,9.621 h2
  text "BAT" at 16.7,9 h2
  text "AEM" at 21.2,9 h2
  text "VMCU" at 28.55,7 h1.2
  text "GND" at 32.25,7 h1.2
  text "NC" at 35.4,7 h1.2
  text "NC" at 37.992,7 h1.2
  text "NC" at 40.5,7 h1.2
  text "NC" at 42.9,7 h1.2
  text "1.7" at 45.45,7 h1.2
  text "1.6" at 48.05,7 h1.2
  text "1.5" at 50.6,7 h1.2
  text "1.4" at 53.15,7 h1.2
  text "1.3" at 55.65,7 h1.2
  text "1.2" at 58.2,7 h1.2
  text "1.1" at 60.8,7 h1.2
  text "1.0" at 63.3,7 h1.2
  text "GND" at 65.3,7 h1.2
  text "3V3" at 68.15,7 h1.2
  text "VMCU" at 28.45,1.2 h1.2
  text "GND" at 32.2,1.2 h1.2
  text "NC" at 35.3,1.2 h1.2
  text "NC" at 38,1.2 h1.2
  text "NC" at 40.5,1.2 h1.2
  text "NC" at 43.1,1.2 h1.2
  text "0.7" at 45.5,1.2 h1.2
  text "0.6" at 48.1,1.2 h1.2
  text "0.5" at 50.5,1.2 h1.2
  text "0.4" at 53.15,1.2 h1.2
  text "0.3" at 55.6,1.2 h1.2
  text "0.2" at 58.2,1.2 h1.2
  text "0.1" at 60.8,1.2 h1.2
  text "0.0" at 63.25,1.2 h1.2
  text "GND" at 65.3,1.2 h1.2
  text "3V3" at 68.15,1.2 h1.2
Bottom Overlay:
  text "PCB5206B Rev A00" at 1.32,34.29 h1 r90
  text "BOARD INFO" at 19.8,15.775 h1.52
  text "BAT" at 7.4,4.1 h1.52
  text "GND" at 7.45,1.45 h1.52
Top Solder:
  lines w0.8: 8.5,-2.4 1.2,-2.4 cw(c1.2,1.2) -2.4,1.2 -2.4,58.8 cw(c1.2,58.8) 1.2,62.4 8.5,62.4 ; 15.5,-2.4 56.5,-2.4 ; 15.5,62.4 56.5,62.4 ; 63.5,-2.4 94.5,-2.4 ; 63.5,62.4 94.5,62.4 ; 101.5,-2.4 113.8,-2.4 ccw(c113.8,1.2) 117.4,1.2 117.4,58.8 ccw(c113.8,58.8) 113.8,62.4 101.5,62.4 ; 0,1.2 ccw(c1.2,1.2) 1.2,0 113.8,0 ccw(c113.8,1.2) 115,1.2 115,58.8 ccw(c113.8,58.8) 113.8,60 1.2,60 ccw(c1.2,58.8) 0,58.8 0,1.2
Bottom Solder:
  lines w0.8: 8.5,-2.4 1.2,-2.4 cw(c1.2,1.2) -2.4,1.2 -2.4,58.8 cw(c1.2,58.8) 1.2,62.4 8.5,62.4 ; 15.5,-2.4 56.5,-2.4 ; 15.5,62.4 56.5,62.4 ; 63.5,-2.4 94.5,-2.4 ; 63.5,62.4 94.5,62.4 ; 101.5,-2.4 113.8,-2.4 ccw(c113.8,1.2) 117.4,1.2 117.4,58.8 ccw(c113.8,58.8) 113.8,62.4 101.5,62.4 ; 0,1.2 ccw(c1.2,1.2) 1.2,0 113.8,0 ccw(c113.8,1.2) 115,1.2 115,58.8 ccw(c113.8,58.8) 113.8,60 1.2,60 ccw(c1.2,58.8) 0,58.8 0,1.2
BOARD OUTLINE 1:
  lines w0.1: 109.5,51.5 cw(c109.1,51.5) 109.1,51.1 cw(c109.1,51.5) 108.7,51.5 108.7,53.5 cw(c109.1,53.5) 109.1,53.9 113.8,53.9 cw(c113.8,53.5) 114.2,53.5 114.2,51.5 cw(c113.8,51.5) 113.8,51.1 cw(c113.8,51.5) 113.4,51.5 113.4,53.1 109.5,53.1 109.5,51.5 ; -2.4,1.2 ccw(c1.2,1.2) 1.2,-2.4 ; -2.4,1.2 ccw(c1.2,1.2) 1.2,-2.4 ; -2.4,1.2 -2.4,58.8 ; -2.4,1.2 -2.4,58.8 ; -2.4,58.8 cw(c1.2,58.8) 1.2,62.4 ; -2.4,58.8 cw(c1.2,58.8) 1.2,62.4 ; 0,1.2 ccw(c1.2,1.2) 1.2,0 ; 0,1.2 ccw(c1.2,1.2) 1.2,0 ; 0,1.2 0,58.8 ; 0,1.2 0,58.8 ; 0,58.8 cw(c1.2,58.8) 1.2,60 ; 0,58.8 cw(c1.2,58.8) 1.2,60 ; 1.2,-2.4 8.5,-2.4 1.2,-2.4 ; 1.2,0 113.8,0 ; 1.2,0 113.8,0 ; 1.2,60 113.8,60 ; 1.2,60 113.8,60 ; 1.2,62.4 8.5,62.4 1.2,62.4 ; 113.8,-2.4 ccw(c113.8,1.2) 117.4,1.2 ; 113.8,-2.4 ccw(c113.8,1.2) 117.4,1.2 ; 113.8,-2.4 101.5,-2.4 113.8,-2.4 ; 113.8,0 ccw(c113.8,1.2) 115,1.2 ; 113.8,0 ccw(c113.8,1.2) 115,1.2 ; 113.8,60 cw(c113.8,58.8) 115,58.8 ; 113.8,60 cw(c113.8,58.8) 115,58.8 ; 113.8,62.4 cw(c113.8,58.8) 117.4,58.8 ; 113.8,62.4 cw(c113.8,58.8) 117.4,58.8 ; 113.8,62.4 101.5,62.4 113.8,62.4 ; 115,1.2 115,58.8 ; 115,1.2 115,58.8 ; 117.4,1.2 117.4,58.8 ; 117.4,1.2 117.4,58.8 ; 15.5,-2.4 56.5,-2.4 15.5,-2.4 ; 15.5,62.4 56.5,62.4 15.5,62.4 ; 63.5,-2.4 94.5,-2.4 63.5,-2.4 ; 63.5,62.4 94.5,62.4 63.5,62.4 ; 108.7,46.9 ccw(c109.1,46.9) 109.1,46.5 113.8,46.5 ccw(c113.8,46.9) 114.2,46.9 114.2,48.9 ccw(c113.8,48.9) 113.8,49.3 ccw(c113.8,48.9) 113.4,48.9 113.4,47.3 109.5,47.3 109.5,48.9 ccw(c109.1,48.9) 109.1,49.3 ccw(c109.1,48.9) 108.7,48.9 108.7,46.9
  text "To Be milled out" at 99.4,44.8 h1
Mechanical 2:
  lines w0.1: -0.25,0 0.25,0 ; 0,-0.25 0,0.25 ; 0,1.2 ccw(c1.2,1.2) 1.2,0 113.8,0 ccw(c113.8,1.2) 115,1.2 115,58.8 ccw(c113.8,58.8) 113.8,60 1.2,60 ccw(c1.2,58.8) 0,58.8 0,1.2
Top Assembly:
  lines w0.1: 0,1.2 ccw(c1.2,1.2) 1.2,0 113.8,0 ccw(c113.8,1.2) 115,1.2 115,58.8 ccw(c113.8,58.8) 113.8,60 1.2,60 ccw(c1.2,58.8) 0,58.8 0,1.2 ; 108.7,46.9 ccw(c109.1,46.9) 109.1,46.5 113.8,46.5 ccw(c113.8,46.9) 114.2,46.9 114.2,48.9 ccw(c113.8,48.9) 113.8,49.3 ccw(c113.8,48.9) 113.4,48.9 113.4,47.3 109.5,47.3 109.5,48.9 ccw(c109.1,48.9) 109.1,49.3 ccw(c109.1,48.9) 108.7,48.9 108.7,46.9 ; 108.7,51.5 ccw(c109.1,51.5) 109.1,51.1 ccw(c109.1,51.5) 109.5,51.5 109.5,53.1 113.4,53.1 113.4,51.5 ccw(c113.8,51.5) 113.8,51.1 ccw(c113.8,51.5) 114.2,51.5 114.2,53.5 ccw(c113.8,53.5) 113.8,53.9 109.1,53.9 ccw(c109.1,53.5) 108.7,53.5 108.7,51.5
Bottom Assembly:
  lines w0.1: 0,1.2 ccw(c1.2,1.2) 1.2,0 113.8,0 ccw(c113.8,1.2) 115,1.2 115,58.8 ccw(c113.8,58.8) 113.8,60 1.2,60 ccw(c1.2,58.8) 0,58.8 0,1.2 ; 108.7,46.9 ccw(c109.1,46.9) 109.1,46.5 113.8,46.5 ccw(c113.8,46.9) 114.2,46.9 114.2,48.9 ccw(c113.8,48.9) 113.8,49.3 ccw(c113.8,48.9) 113.4,48.9 113.4,47.3 109.5,47.3 109.5,48.9 ccw(c109.1,48.9) 109.1,49.3 ccw(c109.1,48.9) 108.7,48.9 108.7,46.9 ; 108.7,51.5 ccw(c109.1,51.5) 109.1,51.1 ccw(c109.1,51.5) 109.5,51.5 109.5,53.1 113.4,53.1 113.4,51.5 ccw(c113.8,51.5) 113.8,51.1 ccw(c113.8,51.5) 114.2,51.5 114.2,53.5 ccw(c113.8,53.5) 113.8,53.9 109.1,53.9 ccw(c109.1,53.5) 108.7,53.5 108.7,51.5
Mechanical 26:
  lines w0.1: -85.787,-32.669 -80.787,-32.669 ; -85.787,14.331 -80.787,14.331 ; -85.775,61.331 -80.787,61.331 ; -14.58,-79.7 -14.58,-74.7 ; -14.58,105.3 -14.58,110.3 ; 56.72,-79.7 56.72,-74.7 ; 56.72,105.3 56.72,110.3 ; 127.92,-79.7 127.92,-74.7 ; 127.92,105.3 127.92,110.3 ; 194.213,-32.669 199.213,-32.669 ; 194.213,14.331 199.213,14.331 ; 194.213,61.331 199.201,61.331 ; -85.775,-79.7 -85.775,110.292 199.213,110.292 199.213,-79.7 -85.775,-79.7 ; -80.787,-74.7 -80.787,105.3 194.213,105.3 194.213,-74.7 -80.787,-74.7
  text "1" at -52.887,106.872 h1.5
  text "2" at 19.42,106.872 h1.5
  text "3" at 92.02,106.872 h1.5
  text "4" at 162.82,106.872 h1.5
  text "D" at 196.211,87.731 h1.5
  text "D" at -83.9,86.526 h1.5
  text "C" at -83.9,39.031 h1.5
  text "C" at 196.084,39.031 h1.5
  text "B" at -83.9,-8.569 h1.5
  text "B" at 196.084,-8.569 h1.5
  text "A" at -83.9,-56.069 h1.5
  text "A" at 196.084,-56.069 h1.5
  text "1" at -51.668,-78.142 h1.5
  text "2" at 19.42,-78.142 h1.5
  text "3" at 91.72,-78.142 h1.5
  text "4" at 162.42,-78.142 h1.5
Mechanical 27:
  circle w0.152: c110.149,-53.169 r0.762
  circle w0.152: c110.149,-53.169 r1.778
  circle w0.254: c78.164,-67.625 r2.962
  lines w0.1: 74.116,-74.56 74.116,-47.7 114.13,-47.7 ; 74.116,-60.336 194.08,-60.336 ; 74.13,-56.7 114.13,-56.7 ; 94.411,-74.509 94.411,-60.412 ; 94.411,-56.653 94.411,-47.737 ; 99.151,-53.169 106.517,-53.169 ; 107.863,-53.169 112.435,-53.169 ; 174.13,-60.31 174.13,-56.7 ; 184.13,-56.7 184.13,-47.7 ; 194.13,-56.7 114.13,-56.7 ; 194.13,-47.7 114.13,-47.7 ; 114.13,-56.7 114.13,-47.7 ; 99.913,-53.931 105.73,-54.947 105.755,-51.391 99.913,-52.407 99.913,-53.931
  text "SIZE" at 76.13,-49.7 h1.52
  text "DOC NO" at 116.13,-49.7 h1.52
  text "REV" at 186.13,-49.7 h1.52
  text "PROJECTION" at 95.427,-50.049 h1.52
  text "A" at 187.747,-54.762 h2.54
  text "BRD5206B (PCB5206B Rev A00)" at 116.452,-55.062 h2.54
  text "A4" at 78.78,-55.074 h2.54
  text "REF" at 76.13,-58.7 h1.52
  text "SHEET" at 175.13,-58.7 h1.5
  text "1 of 2" at 184.797,-59.262 h1.5
  text "This drawing is confidential and is supplied on the express" at 94.893,-63.307 h1.52
  text "condition that it shall not be loaned, copied or disclosed to any" at 94.893,-65.847 h1.52
  text "other person or used for any purpose without the written consent of" at 94.893,-68.387 h1.52
  text "C" at 77.571,-68.641 h2.03
  text "2021" at 82.651,-68.794 h2.54
  text "SILICON LABS" at 95.325,-72.68 h2.54
Mechanical 28:
  lines w0.1: -85.787,-32.669 -80.787,-32.669 ; -85.787,14.331 -80.787,14.331 ; -85.775,61.331 -80.787,61.331 ; -80.812,-74.7 -80.812,105.3 ; -80.787,-74.7 194.213,-74.7 194.213,105.3 -80.787,105.3 ; -14.58,-79.7 -14.58,-74.7 ; -14.58,105.3 -14.58,110.3 ; 56.72,-79.7 56.72,-74.7 ; 56.72,105.3 56.72,110.3 ; 127.92,-79.7 127.92,-74.7 ; 127.92,105.3 127.92,110.3 ; 194.213,-32.669 199.213,-32.669 ; 194.213,14.331 199.213,14.331 ; 194.213,61.331 199.213,61.331 ; -85.775,-79.7 199.213,-79.7 199.213,110.292 -85.775,110.292 -85.775,-79.7
  text "4" at -51.871,106.872 h1.5
  text "3" at 20.436,106.872 h1.5
  text "2" at 93.036,106.872 h1.5
  text "1" at 163.836,106.872 h1.5
  text "D" at 197.227,87.731 h1.5
  text "D" at -82.884,86.526 h1.5
  text "C" at -82.884,39.031 h1.5
  text "C" at 197.227,37.431 h1.5
  text "B" at -82.884,-8.569 h1.5
  text "B" at 197.227,-9.669 h1.5
  text "A" at -82.884,-56.069 h1.5
  text "A" at 197.1,-56.069 h1.5
  text "4" at -50.652,-78.142 h1.5
  text "3" at 20.436,-78.142 h1.5
  text "2" at 92.584,-78.142 h1.5
  text "1" at 163.436,-78.142 h1.5
Mechanical 29:
  circle w0.152: c3.291,-53.233 r0.762
  circle w0.152: c3.291,-53.233 r1.778
  circle w0.254: c35.276,-67.69 r2.962
  lines w0.1: -80.69,-56.764 -0.69,-56.764 ; -80.69,-47.764 -0.69,-47.764 ; -80.64,-60.4 39.324,-60.4 ; -70.69,-56.764 -70.69,-47.764 ; -60.69,-60.374 -60.69,-56.764 ; 1.005,-53.233 5.577,-53.233 ; 6.923,-53.233 14.289,-53.233 ; 19.029,-74.573 19.029,-60.476 ; 19.029,-56.717 19.029,-47.801 ; 39.31,-56.764 -0.69,-56.764 ; 39.31,-47.764 -0.69,-47.764 ; 39.324,-74.624 39.324,-47.7 ; -0.69,-56.764 -0.69,-47.764 ; 7.685,-51.455 7.71,-55.011 13.527,-53.995 13.527,-52.471 7.685,-51.455
  text "REV" at -72.69,-49.764 h1.52
  text "DOC NO" at -2.69,-49.764 h1.52
  text "SIZE" at 37.31,-49.764 h1.52
  text "PROJECTION" at 18.013,-50.113 h1.52
  text "A" at -72.411,-54.685 h2.54
  text "BRD5206B" at -5.19,-55.138 h2.54
  text "A4" at 34.66,-55.138 h2.54
  text "SHEET" at -61.69,-58.764 h1.5
  text "REF" at 37.31,-58.764 h1.52
  text "2 of 2" at -71.403,-59.462 h1.5
  text "This drawing is confidential and is supplied on the express" at 18.547,-63.372 h1.52
  text "condition that it shall not be loaned, copied or disclosed to any" at 18.547,-65.912 h1.52
  text "other person or used for any purpose without the written consent of" at 18.547,-68.452 h1.52
  text "C" at 35.869,-68.706 h2.03
  text "2021" at 30.789,-68.858 h2.54
  text "SILICON LABS" at 18.115,-72.744 h2.54
Mechanical 30:
  lines w0.1: 74.116,-47.7 74.116,-26.86 194.116,-26.86 ; 74.116,-43.764 114.116,-43.764 ; 74.116,-39.764 114.116,-39.764 ; 74.116,-35.764 114.116,-35.764 ; 114.116,-39.765 194.116,-39.765 ; 114.116,-31.764 194.116,-31.764 ; 114.123,-47.7 114.123,-26.86
  text "CUSTOMER" at 115.225,-28.777 h1.27
  text "PROJECT NO" at 75.601,-29.793 h1.52
  text "SILICON LABS" at 133.005,-30.301 h2.03
  text "DRAWING TITLE" at 115.453,-33.704 h1.52
  text "BRD5206B" at 76.871,-34.238 h3.3
  text "EFM8BB52 Busy Bee STK" at 117.055,-37.726 h2.03
  text "DATE" at 75.601,-37.921 h1.52
  text "'.Print_Date'" at 93.889,-38.937 h1.52
  text "SHEET NAME" at 115.25,-41.858 h1.52
  text "DRAWN" at 75.601,-41.985 h1.52
  text "CHECK" at 75.601,-46.049 h1.52
Mechanical 98:
  circle w0.013: c106.204,55.515 r1.25
  circle w0.013: c64.691,-0.468 r2
  circle w0.013: c35.291,-0.468 r2
  circle w0.013: c64.691,60.332 r2
  circle w0.013: c67.035,17.823 r1.25
  circle w0.013: c35.291,60.332 r2
  circle w0.013: c27.061,15.728 r1.25
  circle w0.013: c5.674,38.659 r1.25
  circle w0.013: c103.353,13.016 r1.25
  circle w0.013: c13.683,1.617 r1.25
  circle w0.013: c15.5,39 r1.55
  circle w0.013: c15.5,39 r1.55
  circle w0.013: c112,3.001 r1.55
  circle w0.013: c112,57.001 r1.55
  lines w0.013: 67.291,55.355 67.291,65.332 ; 30.291,-5.468 69.691,-5.468 69.691,4.532 30.291,4.532 30.291,-5.468 ; 30.291,55.332 69.691,55.332 69.691,65.332 30.291,65.332 30.291,55.332
  text "Pressure" at 47.484,59.897 h1.52
  text "Hole" at 111.365,56.722 h0.76
  text "Pressure / (NM)" at 105.396,54.944 h0.51
  text "Pressure" at 4.812,38.561 h0.51
  text "Guide / hole" at 14.718,38.434 h0.76
  text "Guide / hole" at 14.718,38.434 h0.76
  text "Pressure / (NM)" at 66.153,17.352 h0.51
  text "Pressure / (NM)" at 25.64,15.193 h0.51
  text "Pressure" at 102.475,12.78 h0.51
  text "Guide / hole" at 111.111,2.366 h0.76
  text "Pressure / (NM)" at 12.813,1.096 h0.51
  text "Pressure" at 47.484,-1.317 h1.52
Mechanical 99:
  drawing of 661 lines, arcs and shapes, not listed
  text "Hole" at 111.365,56.722 h0.76
  text "P1-1" at 15.48,54.74 h0.51
  text "TPJ814" at 83.577,54.105 h0.51
  text "TPJ613" at 11.949,53.699 h0.51
  text "TPJ612" at 9.384,53.623 h0.51
  text "TPJ415" at 106.412,53.572 h0.38
  text "P2-1" at 87.031,53.547 h0.51
  text "P2-7" at 93.127,53.547 h0.51
  text "P2-3" at 89.063,53.521 h0.51
  text "TPJ412" at 103.897,53.521 h0.38
  text "P1-2" at 18.02,53.445 h0.51
  text "TPJ812" at 80.859,53.267 h0.51
  text "TPJ811" at 77.125,52.48 h0.51
  text "P1-3" at 15.454,52.2 h0.51
  text "TPJ414" at 104.862,51.845 h0.38
  text "TPJ413" at 102.805,51.819 h0.38
  text "P2-6" at 92.111,51.769 h0.51
  text "P2-2" at 88.047,51.743 h0.51
  text "P2-4" at 90.079,51.743 h0.51
  text "TPJ813" at 84.618,51.515 h0.51
  text "TPJ611" at 9.384,51.108 h0.51
  text "P1-4" at 17.994,50.905 h0.51
  text "TPJ820" at 79.386,50.727 h0.51
  text "P1-5" at 15.48,49.635 h0.51
  text "TPJ614" at 6.767,49.61 h0.51
  text "P1-6" at 17.994,48.365 h0.51
  text "TPJ817" at 101.865,48.136 h0.51
  text "TPJ507" at 72.807,47.857 h0.38
  text "TPJ503" at 74.814,47.857 h0.38
  text "TPJ505" at 76.846,47.857 h0.38
  text "TPJ606" at 96.607,46.993 h0.51
  text "P1-8" at 18.02,45.825 h0.51
  text "TPJ500" at 70.826,45.673 h0.38
  text "TPJ506" at 72.833,45.647 h0.38
  text "TPJ502" at 74.839,45.647 h0.38
  text "TPJ504" at 76.846,45.647 h0.38
  text "TPJ908" at 43.14,45.419 h0.51
  text "Support / pin" at 21.703,44.784 h1.02
  text "Support / pin" at 85.711,44.657 h1.02
  text "TPJ607" at 65.848,43.895 h0.51
  text "TPJ909" at 41.845,43.234 h0.51
  text "TPJ650" at 107.478,43.031 h0.51
  text "TPJ501" at 72.833,42.929 h0.38
  text "TPJ807" at 92.67,42.091 h0.51
  text "TPJ902" at 23.836,41.202 h0.51
  text "TPJ905" at 53.884,40.923 h0.51
  text "TPJ818" at 70.75,40.77 h0.51
  text "TPJ651" at 107.453,39.475 h0.51
  text "TPJ609" at 85.355,39.323 h0.51
  text "TPJ956" at 51.954,39.043 h0.51
  text "Guide / hole" at 14.718,38.434 h0.76
  text "Guide / hole" at 14.718,38.434 h0.76
  text "TPJ901" at 43.293,38.357 h0.51
  text "TPJ900" at 40.778,37.697 h0.51
  text "TPJ930" at 35.444,36.833 h0.51
  text "TPJ931" at 38.238,36.833 h0.51
  text "Cutout" at -9.057,36.275 h1.52
  text "TPJ604" at 9.612,34.192 h0.51
  text "TPJ912" at 49.947,34.065 h0.51
  text "TPJ960" at 53.122,32.414 h0.51
  text "TPJ600" at 13.575,32.084 h0.51
  text "TPJ603" at 9.612,31.576 h0.51
  text "TPJ913" at 49.947,30.306 h0.51
  text "TPJ961" at 53.173,29.874 h0.51
  text "TPJ910" at 47.204,29.442 h0.51
  text "TPJ601" at 8.698,29.086 h0.51
  text "TPJ602" at 11.238,29.061 h0.51
  text "TPJ911" at 44.69,28.655 h0.51
  text "TPJ959" at 53.707,27.41 h0.51
  text "TPJ957" at 50.989,27.385 h0.51
  text "TPJ954" at 42.505,27.283 h0.51
  text "TPJ616" at 14.895,25.734 h0.51
  text "TPJ615" at 11.263,25.708 h0.51
  text "TPJ958" at 52.386,25.251 h0.51
  text "TPJ953" at 41.21,25.048 h0.51
  text "TPJ955" at 43.724,25.022 h0.51
  text "TPJ952" at 46.214,25.022 h0.51
  text "TPJ608" at 33.742,20.323 h0.51
  text "TPJ950" at 23.684,16.894 h0.51
  text "TPJ653" at 51.167,15.878 h0.51
  text "TPJ652" at 60.539,15.878 h0.51
  text "TPJ804" at 93.407,11.662 h0.51
  text "TPJ803" at 96.023,11.129 h0.51
  text "TPJ404" at 72.198,10.29 h0.51
  text "TPJ403" at 76.49,10.265 h0.51
  text "TPJ402" at 80.732,10.214 h0.51
  text "Cutout" at 114.413,9.986 h1.52
  text "Support / pin" at 103.745,9.859 h1.02
  text "Support / pin" at 21.703,9.732 h1.02
  text "TPJ808" at 92.467,9.224 h0.51
  text "TPJ801" at 95.718,8.462 h0.51
  text "TPJ802" at 92.467,6.684 h0.51
  text "TPJ405" at 73.315,6.049 h0.51
  text "TPJ810" at 94.931,5.845 h0.51
  text "Guide / hole" at 111.111,2.366 h0.76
